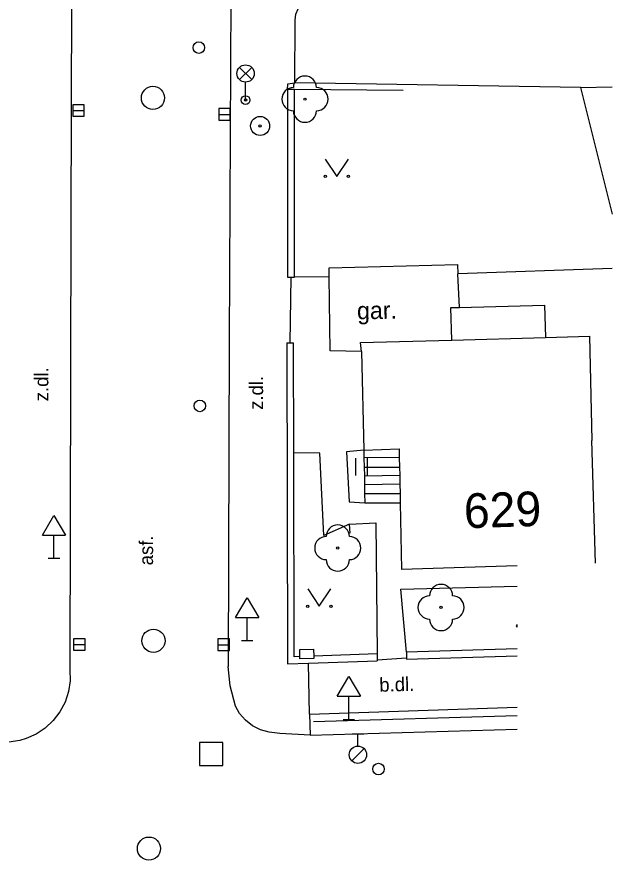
# Model space of a CAD drawing. Extents: x -642282 to -641982, y -1041678 to -1041427.
# Drawn here: x -642009.58 to -641983.82, y -1041502.17 to -1041465.69 of the extents above; entities that cross this region are included whole.
import ezdxf

# ---------------------------------------------------------------- set-up
doc = ezdxf.new("R2010")
doc.units = 0
for name, color, linetype in [('Budovy', 7, 'Continuous'), ('Ploty', 7, 'Continuous'), ('Pol_bod_pole', 7, 'Continuous'), ('Popis objektů', 7, 'Continuous'), ('Popis povrchů', 7, 'Continuous'), ('Popis ČP_ ČE', 7, 'Continuous'), ('Pris-HUP', 7, 'Continuous'), ('Rozhraní ploch 1', 7, 'Continuous'), ('Rozhraní ploch 2', 7, 'Continuous'), ('Vstup na pozemky', 7, 'Continuous'), ('Zeleň - stromy', 7, 'Continuous'), ('Znaky doprava', 7, 'Continuous'), ('Znaky kanalizace', 7, 'Continuous'), ('Znaky voda', 7, 'Continuous'), ('Značky doprava', 7, 'Continuous'), ('Značky KM', 7, 'Continuous'), ('Šachty ner_', 7, 'Continuous')]:
    doc.layers.add(name, color=color, linetype=linetype)

msp = doc.modelspace()

# ---------------------------------------------------------------- linework, layer by layer
at = {"layer": 'Budovy'}
for p, q in [((-641996.06, -1041476.54), (-641990.51, -1041476.4)), ((-641996.06, -1041476.94), (-641996.06, -1041476.54)), ((-641990.51, -1041476.4), (-641990.49, -1041476.81)), ((-641996.02, -1041480.14), (-641996.06, -1041476.94)), ((-641990.43, -1041478.26), (-641990.49, -1041476.81)), ((-641990.8, -1041478.27), (-641990.43, -1041478.26)), ((-641990.76, -1041479.67), (-641990.8, -1041478.27)), ((-641990.43, -1041478.26), (-641986.74, -1041478.16)), ((-641986.74, -1041478.16), (-641986.7, -1041479.56)), ((-641986.7, -1041479.56), (-641984.8, -1041479.51)), ((-641984.8, -1041479.51), (-641984.7, -1041484.01)), ((-641994.71, -1041479.78), (-641990.76, -1041479.67)), ((-641994.66, -1041480.16), (-641994.71, -1041479.78)), ((-641990.76, -1041479.67), (-641986.7, -1041479.56)), ((-641994.66, -1041480.16), (-641996.02, -1041480.14)), ((-641994.66, -1041480.16), (-641994.57, -1041484.43)), ((-641984.54, -1041489.33), (-641984.7, -1041484.01)), ((-641994.57, -1041484.43), (-641993.04, -1041484.37)), ((-641993.04, -1041484.37), (-641993.03, -1041484.75)), ((-641993.03, -1041484.75), (-641993.02, -1041485.17)), ((-641993.02, -1041485.17), (-641993.01, -1041485.52)), ((-641993.01, -1041485.52), (-641993, -1041485.89)), ((-641993, -1041485.89), (-641992.99, -1041486.31)), ((-641992.99, -1041486.31), (-641992.99, -1041486.71)), ((-641992.99, -1041486.71), (-641992.93, -1041489.6)), ((-641987.935, -1041489.439), (-641992.93, -1041489.6))]:
    msp.add_line(p, q, dxfattribs=at)
at = {"layer": 'Ploty'}
for p, q in [((-641997.86, -1041468.83), (-641997.85, -1041468.58)), ((-641997.85, -1041468.58), (-641997.55, -1041468.54)), ((-641985.19, -1041468.74), (-641997.55, -1041468.54)), ((-641997.86, -1041468.83), (-641997.86, -1041476.95)), ((-641997.56, -1041476.95), (-641997.56, -1041468.833)), ((-641997.9, -1041479.79), (-641997.87, -1041493.68)), ((-641997.59, -1041484.552), (-641997.6, -1041479.789)), ((-641997.571, -1041493.37), (-641997.59, -1041484.552)), ((-641987.935, -1041493.035), (-641992.719, -1041493.18)), ((-641997.329, -1041493.362), (-641997.571, -1041493.37)), ((-641993.99, -1041493.25), (-641996.729, -1041493.342)), ((-641992.71, -1041493.48), (-641987.935, -1041493.335)), ((-641987.935, -1041495.933), (-641996.74, -1041496.18))]:
    msp.add_line(p, q, dxfattribs=at)
for points in [[(-641997.54, -1041465.83), (-641997.508, -1041465.578), (-641997.4, -1041465.349), (-641997.226, -1041465.164), (-641997.003, -1041465.042), (-641996.754, -1041464.995), (-641996.64, -1041465)], [(-641992.86, -1041468.873), (-641997.56, -1041468.833), (-641997.86, -1041468.83)], [(-641997.86, -1041476.95), (-641997.72, -1041476.95), (-641997.56, -1041476.95)], [(-641997.9, -1041479.79), (-641997.759, -1041479.79), (-641997.6, -1041479.789)], [(-641993.99, -1041493.25), (-641993.99, -1041493.5), (-641993.98, -1041493.55)], [(-641992.719, -1041493.18), (-641992.712, -1041493.425), (-641992.71, -1041493.48)], [(-641997.87, -1041493.68), (-641996.958, -1041493.65), (-641993.98, -1041493.55)]]:
    msp.add_lwpolyline(points, dxfattribs=at)
at = {"layer": 'Pol_bod_pole'}
for radius in [0.412, 0.05]:
    msp.add_circle((-641999.05, -1041470.41), radius, dxfattribs=at)
at = {"layer": 'Pris-HUP'}
msp.add_lwpolyline([(-641997.329, -1041493.362), (-641997.337, -1041493.064), (-641996.737, -1041493.047), (-641996.729, -1041493.342), (-641996.726, -1041493.447), (-641997.326, -1041493.464), (-641997.329, -1041493.362)], dxfattribs=at)
at = {"layer": 'Rozhraní ploch 1'}
for p, q in [((-642007.15, -1041448.28), (-642007.24, -1041474.56)), ((-642000.28, -1041455.75), (-642000.39, -1041479.71)), ((-642007.24, -1041474.56), (-642007.28, -1041493.93)), ((-641996.06, -1041476.94), (-641997.56, -1041476.95)), ((-642000.39, -1041479.71), (-642000.43, -1041493.8)), ((-641994.57, -1041484.43), (-641994.56, -1041484.77)), ((-641993.03, -1041484.75), (-641994.56, -1041484.77)), ((-641994.56, -1041484.77), (-641994.55, -1041485.17)), ((-641994.55, -1041485.17), (-641993.02, -1041485.17)), ((-641994.55, -1041485.17), (-641994.54, -1041485.54)), ((-641994.54, -1041485.54), (-641993.01, -1041485.52)), ((-641994.54, -1041485.54), (-641994.54, -1041485.92)), ((-641994.54, -1041485.92), (-641993, -1041485.89)), ((-641994.54, -1041485.92), (-641994.53, -1041486.31)), ((-641994.53, -1041486.31), (-641992.99, -1041486.31)), ((-641994.53, -1041486.31), (-641994.52, -1041486.72)), ((-641994.52, -1041486.72), (-641992.99, -1041486.71)), ((-641995.18, -1041487.64), (-641994.04, -1041487.58)), ((-641994.04, -1041487.58), (-641993.99, -1041493.25)), ((-641995.16, -1041488.02), (-641995.18, -1041487.64)), ((-641992.96, -1041490.45), (-641987.935, -1041490.313)), ((-641992.719, -1041493.18), (-641992.96, -1041490.45)), ((-641996.91, -1041495.86), (-641987.935, -1041495.546)), ((-641996.91, -1041495.86), (-641996.89, -1041496.76)), ((-641996.89, -1041496.76), (-641987.935, -1041496.509)), ((-642009.451, -1041496.993), (-642010.75, -1041497.18))]:
    msp.add_line(p, q, dxfattribs=at)
for points in [[(-641995.18, -1041487.64), (-641996.3, -1041488.13), (-641996.46, -1041484.56), (-641997.59, -1041484.552)], [(-641994.57, -1041484.43), (-641995.31, -1041484.5), (-641995.2, -1041486.67), (-641994.52, -1041486.72)], [(-642007.28, -1041493.93), (-642007.27, -1041494.407), (-642007.34, -1041494.878), (-642007.488, -1041495.331), (-642007.71, -1041495.753), (-642007.998, -1041496.132), (-642008.346, -1041496.458), (-642008.744, -1041496.721), (-642009.18, -1041496.914), (-642009.451, -1041496.993)], [(-642000.111, -1041495.503), (-642000.349, -1041494.63), (-642000.43, -1041493.8)], [(-641998.666, -1041496.63), (-641999.04, -1041496.533), (-641999.386, -1041496.361), (-641999.689, -1041496.122), (-641999.937, -1041495.825), (-642000.111, -1041495.503)], [(-641996.89, -1041496.76), (-641998.192, -1041496.694), (-641998.666, -1041496.63)]]:
    msp.add_lwpolyline(points, dxfattribs=at)
at = {"layer": 'Rozhraní ploch 2'}
for p, q in [((-641985.19, -1041468.74), (-641983.819, -1041468.723)), ((-641985.19, -1041468.74), (-641983.819, -1041474.229)), ((-641983.819, -1041476.571), (-641990.49, -1041476.81)), ((-641996.91, -1041495.86), (-641996.958, -1041493.65))]:
    msp.add_line(p, q, dxfattribs=at)
at = {"layer": 'Vstup na pozemky'}
for p, q in [((-641997.55, -1041468.54), (-641997.54, -1041465.83)), ((-641997.72, -1041476.95), (-641997.759, -1041479.79)), ((-641993.99, -1041493.5), (-641992.712, -1041493.425))]:
    msp.add_line(p, q, dxfattribs=at)
at = {"layer": 'Zeleň - stromy'}
for centre in [(-641997.11, -1041469.25), (-641995.69, -1041488.67), (-641991.22, -1041491.24)]:
    msp.add_circle(centre, 0.05, dxfattribs=at)
for centre, start, end in [((-641997.11, -1041468.75), 0, 180), ((-641997.61, -1041469.25), 90, 270), ((-641996.61, -1041469.25), 270, 90), ((-641997.11, -1041469.75), 180, 0), ((-641995.69, -1041488.17), 0, 180), ((-641996.19, -1041488.67), 90, 270), ((-641995.19, -1041488.67), 270, 90), ((-641995.69, -1041489.17), 180, 0), ((-641991.22, -1041490.74), 0, 180), ((-641991.72, -1041491.24), 90, 270), ((-641990.72, -1041491.24), 270, 90), ((-641991.22, -1041491.74), 180, 0)]:
    msp.add_arc(centre, 0.5, start, end, dxfattribs=at)
at = {"layer": 'Znaky doprava'}
for p, q in [((-641999.945, -1041467.875), (-641999.415, -1041468.405)), ((-641999.945, -1041468.405), (-641999.415, -1041467.875)), ((-641999.68, -1041469.29), (-641999.68, -1041468.515))]:
    msp.add_line(p, q, dxfattribs=at)
for centre, radius in [((-641999.68, -1041468.14), 0.375), ((-641999.68, -1041469.29), 0.19), ((-641999.68, -1041469.29), 0.05)]:
    msp.add_circle(centre, radius, dxfattribs=at)
at = {"layer": 'Znaky kanalizace'}
for p, q in [((-642007.16, -1041469.74), (-642006.66, -1041469.74)), ((-642000.84, -1041469.91), (-642000.34, -1041469.91)), ((-642007.12, -1041492.84), (-642006.62, -1041492.84)), ((-642000.88, -1041492.85), (-642000.38, -1041492.85))]:
    msp.add_line(p, q, dxfattribs=at)
for points in [[(-642007.16, -1041469.99), (-642006.66, -1041469.99), (-642006.66, -1041469.49), (-642007.16, -1041469.49)], [(-642000.84, -1041470.16), (-642000.34, -1041470.16), (-642000.34, -1041469.66), (-642000.84, -1041469.66)], [(-642007.12, -1041493.09), (-642006.62, -1041493.09), (-642006.62, -1041492.59), (-642007.12, -1041492.59)], [(-642000.88, -1041493.1), (-642000.38, -1041493.1), (-642000.38, -1041492.6), (-642000.88, -1041492.6)]]:
    msp.add_lwpolyline(points, close=True, dxfattribs=at)
for centre in [(-642003.687, -1041469.195), (-642003.664, -1041492.681), (-642003.86, -1041501.67)]:
    msp.add_circle(centre, 0.5, dxfattribs=at)
at = {"layer": 'Znaky voda'}
for p, q in [((-641995.07, -1041496.71), (-641994.57, -1041496.71)), ((-641994.82, -1041497.235), (-641994.82, -1041496.71)), ((-641995.085, -1041497.875), (-641994.555, -1041497.345))]:
    msp.add_line(p, q, dxfattribs=at)
for centre, radius in [((-642001.7, -1041467.02), 0.25), ((-642001.66, -1041482.52), 0.25), ((-641994.82, -1041497.61), 0.375), ((-641993.93, -1041498.23), 0.25)]:
    msp.add_circle(centre, radius, dxfattribs=at)
at = {"layer": 'Značky doprava'}
for p, q in [((-642008.47, -1041488.11), (-642007.97, -1041487.26)), ((-642007.97, -1041487.26), (-642007.47, -1041488.11)), ((-642008.47, -1041488.11), (-642007.47, -1041488.11)), ((-642007.97, -1041489.11), (-642007.97, -1041488.11)), ((-642008.22, -1041489.11), (-642007.72, -1041489.11)), ((-642000.11, -1041491.67), (-641999.61, -1041490.82)), ((-641999.61, -1041490.82), (-641999.11, -1041491.67)), ((-642000.11, -1041491.67), (-641999.11, -1041491.67)), ((-641999.61, -1041492.67), (-641999.61, -1041491.67)), ((-641999.86, -1041492.67), (-641999.36, -1041492.67)), ((-641995.71, -1041495.08), (-641995.21, -1041494.23)), ((-641995.21, -1041494.23), (-641994.71, -1041495.08)), ((-641995.71, -1041495.08), (-641994.71, -1041495.08)), ((-641995.21, -1041496.08), (-641995.21, -1041495.08)), ((-641995.46, -1041496.08), (-641994.96, -1041496.08))]:
    msp.add_line(p, q, dxfattribs=at)
at = {"layer": 'Značky KM'}
for p, q in [((-641996.23, -1041471.84), (-641995.73, -1041472.59)), ((-641995.73, -1041472.59), (-641995.23, -1041471.84)), ((-641994.91, -1041485.53), (-641994.91, -1041484.78)), ((-641994.41, -1041485.53), (-641994.41, -1041484.78)), ((-641996.99, -1041490.44), (-641996.49, -1041491.19)), ((-641996.49, -1041491.19), (-641995.99, -1041490.44))]:
    msp.add_line(p, q, dxfattribs=at)
msp.add_lwpolyline([(-641987.935, -1041492.088), (-641987.935, -1041491.992)], dxfattribs=at)
for centre in [(-641996.23, -1041472.59), (-641995.23, -1041472.59), (-641996.99, -1041491.19), (-641995.99, -1041491.19)]:
    msp.add_circle(centre, 0.05, dxfattribs=at)
msp.add_arc((-641987.92, -1041492.04), 0.05, 107.0633, 252.9367, dxfattribs=at)
at = {"layer": 'Šachty ner_'}
msp.add_lwpolyline([(-642001.67, -1041498.08), (-642000.67, -1041498.08), (-642000.67, -1041497.08), (-642001.67, -1041497.08)], close=True, dxfattribs=at)

# ---------------------------------------------------------------- texts
at = {"layer": 'Popis objektů'}
msp.add_text('gar.', height=0.75, rotation=1.1116, dxfattribs=at).set_placement((-641994.85, -1041478.777))
at = {"layer": 'Popis povrchů'}
for s, rotation, p in [('z.dl.', 89.8609, (-642008.215, -1041482.321)), ('z.dl.', 89.8373, (-641998.923, -1041482.692)), ('asf.', 89.7489, (-642003.684, -1041489.419)), ('b.dl.', 1.6073, (-641993.887, -1041494.889))]:
    msp.add_text(s, height=0.6, rotation=rotation, dxfattribs=at).set_placement(p)
at = {"layer": 'Popis ČP_ ČE'}
msp.add_text('629', height=1.5, rotation=1.8432, dxfattribs=at).set_placement((-641990.21, -1041487.816))

doc.saveas('drawing.dxf')
